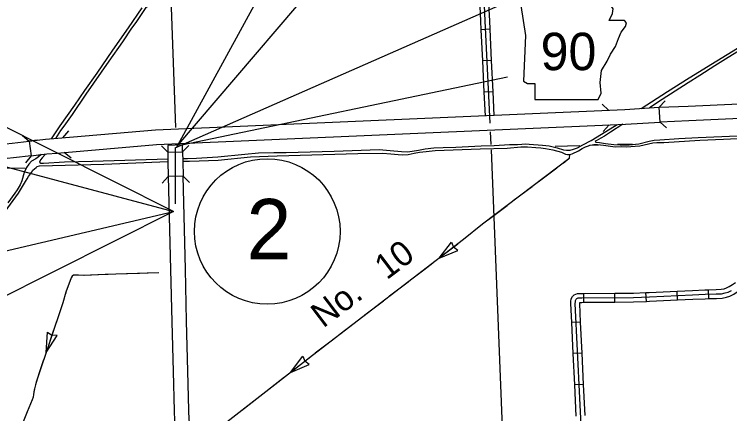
# Model space of a CAD drawing. Extents: x -5566 to 1759129, y -3726 to 731467.
# Drawn here: x -4834.6 to -4742.8, y 279.5 to 330.8 of the extents above; entities that cross this region are included whole.
import ezdxf

# ---------------------------------------------------------------- set-up
doc = ezdxf.new("R2010")
doc.units = 0
doc.layers.add('Default', color=7, linetype='Continuous')

msp = doc.modelspace()

# ---------------------------------------------------------------- linework, layer by layer
at = {"layer": 'Default'}
for p, q in [((-5045.078, 367.089), (-4814.177, 305.513)), ((-4773.531, 328.908), (-4774.669, 328.854)), ((-4773.339, 324.903), (-4774.477, 324.849)), ((-4773.148, 320.898), (-4774.286, 320.844)), ((-4813.973, 313.686), (-4813.973, 306.506)), ((-5037.982, 253.015), (-4814.177, 305.513)), ((-4780.075, 299.507), (-4778.488, 301.574)), ((-4778.488, 301.574), (-4778.222, 300.933)), ((-4780.075, 299.507), (-4777.667, 300.504)), ((-4777.667, 300.504), (-4778.217, 300.926)), ((-4761.516, 293.849), (-4761.524, 294.988)), ((-4757.507, 293.876), (-4757.515, 295.015)), ((-4753.475, 293.973), (-4753.531, 295.11)), ((-4749.471, 294.16), (-4749.524, 295.298)), ((-4745.473, 294.326), (-4745.51, 295.464)), ((-4761.915, 291.318), (-4763.053, 291.264)), ((-4830.53, 287.413), (-4830.363, 290.014)), ((-4830.53, 287.413), (-4829.084, 289.582)), ((-4830.363, 290.014), (-4829.785, 289.629)), ((-4829.084, 289.582), (-4829.776, 289.627)), ((-4799.146, 284.84), (-4797.576, 286.921)), ((-4797.576, 286.921), (-4797.306, 286.282)), ((-4761.727, 287.312), (-4762.865, 287.259)), ((-4799.146, 284.84), (-4796.746, 285.858)), ((-4796.746, 285.858), (-4797.3, 286.275)), ((-4761.538, 283.307), (-4762.676, 283.253))]:
    msp.add_line(p, q, dxfattribs=at)
for points in [[(-4813.759, 313.857), (-4581.459, 585.645), (-4581.459, 585.645)], [(-4813.973, 313.686), (-4397.101, 497.071), (-4397.101, 497.071)], [(-4813.622, 314.016), (-4813.622, 314.016), (-4788.986, 359.2), (-4781.856, 351.37)], [(-4696.252, 355.061), (-4696.632, 354.686), (-4697.139, 354.156), (-4698.831, 353.208), (-4705.395, 349.146), (-4717.477, 341.348), (-4731.156, 332.251), (-4732.102, 331.642), (-4732.867, 331.328), (-4733.4, 331.136), (-4733.902, 330.892), (-4734.572, 330.459), (-4742.996, 325.302), (-4744.672, 324.236), (-4746.615, 322.956), (-4748.105, 322.025), (-4751.473, 319.9), (-4753.098, 318.821)], [(-4807.443, 346.646), (-4810.466, 342.198), (-4812.338, 339.431), (-4813.061, 338.397), (-4815.169, 335.265), (-4815.226, 335.212), (-4816.37, 333.578), (-4816.913, 332.809), (-4817.113, 332.456), (-4817.651, 331.767), (-4817.704, 331.713), (-4818.988, 329.775), (-4819.546, 329.036), (-4820.713, 327.31), (-4822.48, 324.819), (-4825.42, 320.583), (-4827.194, 317.972), (-4828.239, 316.463), (-4828.664, 315.919), (-4829.314, 314.906)], [(-4814.599, 335.359), (-4813.909, 316.294)], [(-4773.525, 316.866), (-4774.152, 329.976), (-4774.348, 334.007)], [(-4774.669, 328.854), (-4774.721, 329.948), (-4774.863, 332.859)], [(-4773.531, 328.908), (-4773.583, 330.003), (-4773.725, 332.914)], [(-4754.128, 318.759), (-4750.752, 320.921), (-4747.973, 322.677), (-4744.417, 324.862), (-4740.467, 327.31), (-4736.357, 329.733), (-4733.777, 331.269), (-4732.753, 331.827), (-4731.996, 332.156), (-4731.432, 332.577), (-4730.561, 333.153)], [(-4818.247, 331.657), (-4820.008, 329.083), (-4822, 326.216), (-4824.011, 323.288), (-4825.578, 321.057), (-4826.866, 319.173), (-4828.773, 316.526), (-4829.874, 314.859)], [(-4774.477, 324.849), (-4774.669, 328.854)], [(-4773.339, 324.903), (-4773.531, 328.908)], [(-4814.177, 305.513), (-4814.177, 305.513), (-4860.149, 328.644), (-4861.555, 318.147)], [(-4774.286, 320.844), (-4774.477, 324.849)], [(-4773.148, 320.898), (-4773.339, 324.903)], [(-4813.108, 314.066), (-4771.285, 322.799)], [(-4774.139, 317.783), (-4774.286, 320.844)], [(-4773.001, 317.839), (-4773.148, 320.898)], [(-4751.821, 318.897), (-4751.056, 319.742)], [(-4751.821, 318.897), (-4748.112, 319.035), (-4735.949, 319.604), (-4734.369, 319.692), (-4734.52, 319.478), (-4734.628, 319.185), (-4734.685, 318.866), (-4734.649, 318.572), (-4734.577, 318.335), (-4734.448, 318.093), (-4734.335, 317.944), (-4734.179, 317.802)], [(-4816.483, 315.999), (-4756.262, 318.631), (-4751.821, 318.897)], [(-4759.172, 319.31), (-4758.332, 318.541)], [(-4734.179, 317.802), (-4735.851, 317.708), (-4748.032, 317.139), (-4751.726, 317.001), (-4751.821, 318.897)], [(-4816.361, 314.104), (-4756.151, 316.736), (-4751.726, 317.001)], [(-4750.881, 316.237), (-4751.726, 317.001)], [(-4831.677, 314.67), (-4832.68, 314.552), (-4831.66, 314.672), (-4830.616, 314.796), (-4829.028, 314.931), (-4816.475, 316)], [(-4812.996, 312.306), (-4812.391, 312.302), (-4811.206, 312.381), (-4808.477, 312.534), (-4805.021, 312.875), (-4803.268, 313.057), (-4801.289, 313.072), (-4799.709, 313.092), (-4793.544, 313.266), (-4787.763, 313.469), (-4786.373, 313.34), (-4784.919, 313.218), (-4784.105, 313.189), (-4782.722, 313.4), (-4781.876, 313.564), (-4780.764, 313.682), (-4779.581, 313.749), (-4777.926, 313.778), (-4774.666, 313.94), (-4773.035, 314.006), (-4771.043, 314.1), (-4770.008, 314.134), (-4769.463, 314.153), (-4769.049, 314.19), (-4768.531, 314.164), (-4766.832, 314.042), (-4765.938, 313.93), (-4764.922, 313.676), (-4764.101, 313.43), (-4763.718, 313.369), (-4763.258, 313.404), (-4762.826, 313.507), (-4762.306, 313.695), (-4761.65, 314.089), (-4760.561, 314.615), (-4757.572, 316.454), (-4757.241, 316.688)], [(-4756.501, 316.72), (-4758.065, 315.715), (-4758.853, 315.187), (-4759.336, 314.918), (-4759.645, 314.746), (-4759.939, 314.589), (-4760.061, 314.514), (-4759.958, 314.42), (-4759.505, 314.374), (-4758.726, 314.23), (-4757.664, 314.109), (-4756.846, 314.072), (-4755.696, 314.084), (-4754.458, 314.222), (-4753.124, 314.557), (-4752.474, 314.661), (-4751.744, 314.702), (-4749.307, 314.904), (-4746.846, 315.005), (-4739.766, 315.315)], [(-4758.249, 316.644), (-4759.018, 315.804)], [(-4833.575, 315.257), (-4832.68, 314.552)], [(-4828.356, 314.988), (-4827.622, 315.859)], [(-4812.992, 311.992), (-4812.104, 311.996), (-4808.423, 312.106), (-4804.27, 312.543), (-4800.874, 312.671), (-4790.495, 312.961), (-4787.357, 312.989), (-4786.292, 312.931), (-4785.324, 312.824), (-4784.754, 312.796), (-4784.056, 312.825), (-4783.264, 312.987), (-4782.592, 313.13), (-4781.752, 313.232), (-4780.585, 313.338), (-4774.818, 313.558), (-4771.336, 313.649), (-4769.612, 313.815), (-4768.721, 313.827), (-4767.686, 313.733), (-4767.01, 313.686), (-4766.427, 313.611), (-4765.477, 313.432), (-4764.386, 313.122), (-4763.864, 312.866), (-4763.62, 312.827), (-4763.506, 312.823), (-4763.342, 312.82), (-4763.008, 312.938), (-4762.198, 313.291), (-4761.729, 313.588), (-4761.295, 313.799), (-4760.92, 313.948), (-4760.748, 314.03), (-4760.447, 314.072), (-4760.231, 314.128), (-4759.751, 314.1), (-4758.98, 314.015), (-4757.805, 313.846), (-4757.401, 313.836), (-4756.733, 313.846), (-4756.055, 313.796), (-4754.311, 313.949), (-4753.202, 314.194), (-4752.637, 314.344), (-4752.12, 314.382), (-4751.246, 314.391), (-4746.613, 314.688), (-4743.585, 314.785), (-4740.036, 314.979)], [(-4773.406, 314.127), (-4773.474, 315.749)], [(-4856.545, 312.213), (-4855.815, 312.238), (-4854.039, 312.293), (-4852.828, 312.353), (-4848.711, 312.761), (-4847.151, 312.947), (-4844.684, 313.184), (-4844.182, 313.237), (-4842.093, 313.462), (-4840.463, 313.635), (-4838.392, 313.881), (-4836.555, 314.114), (-4834.901, 314.288), (-4832.68, 314.552), (-4832.456, 312.667)], [(-4832.456, 312.667), (-4831.517, 312.778), (-4831.437, 312.787), (-4830.424, 312.906), (-4829.095, 313.02), (-4816.35, 314.105)], [(-4813.008, 313.173), (-4813.02, 314.071), (-4814.917, 313.983)], [(-4760.589, 314.031), (-4759.622, 314.061)], [(-4757.188, 314.137), (-4755.321, 314.195)], [(-4814.906, 313.14), (-4815.725, 313.931)], [(-4814.917, 313.983), (-4814.906, 313.14), (-4813.008, 313.173)], [(-4814.906, 313.14), (-4814.89, 311.914), (-4814.842, 309.994)], [(-4812.217, 313.992), (-4813.008, 313.173)], [(-4813.008, 313.173), (-4812.991, 311.95), (-4812.944, 310.041)], [(-4771.764, 273.516), (-4773.376, 313.42)], [(-4765.192, 313.888), (-4762.007, 313.987)], [(-4832.456, 312.667), (-4834.69, 312.401), (-4836.336, 312.228), (-4838.16, 311.997), (-4840.251, 311.748), (-4841.892, 311.574), (-4843.98, 311.349), (-4844.493, 311.295), (-4846.948, 311.059), (-4848.505, 310.873), (-4852.687, 310.459), (-4853.963, 310.396), (-4855.753, 310.34), (-4856.481, 310.316), (-4856.545, 312.213)], [(-4831.17, 312.819), (-4831.521, 312.514), (-4831.841, 312.295), (-4832.391, 311.963), (-4832.751, 311.578), (-4833.046, 311.152), (-4833.35, 310.535), (-4833.636, 309.466), (-4833.837, 308.92), (-4834.229, 308.288), (-4834.529, 307.846), (-4835.448, 306.638)], [(-4763.342, 312.82), (-4763.384, 312.316), (-4763.42, 312.254), (-4774.516, 303.871), (-4776.93, 301.919), (-4796.328, 287.04), (-4812.156, 274.681), (-4814.523, 272.847), (-4815.12, 272.263), (-4815.497, 271.946), (-4816.06, 271.595), (-4816.797, 271.127), (-4817.39, 270.57), (-4817.892, 270.067), (-4818.359, 269.474), (-4818.773, 268.881), (-4818.872, 268.556), (-4819.354, 267.923), (-4820.03, 266.944), (-4826.828, 257.914), (-4833.291, 249.226)], [(-4832.456, 312.666), (-4833.161, 311.772)], [(-4830.605, 312.891), (-4831.025, 312.401), (-4831.254, 312.138), (-4831.353, 311.861), (-4831.194, 311.717)], [(-4831.194, 311.717), (-4830.866, 311.702), (-4828.168, 311.872), (-4824.577, 311.977), (-4814.895, 312.292)], [(-4827.324, 312.362), (-4828.195, 313.096)], [(-4763.342, 312.82), (-4763.384, 312.316), (-4763.42, 312.254), (-4764.159, 311.696)], [(-4835.8, 305.522), (-4834.072, 307.871), (-4833.162, 309.363), (-4832.96, 309.719), (-4832.782, 309.988), (-4832.644, 310.189), (-4832.413, 310.531), (-4832.244, 310.817), (-4831.808, 311.173), (-4831.682, 311.309)], [(-4831.682, 311.309), (-4831.364, 311.374), (-4823.099, 311.596), (-4814.89, 311.939)], [(-4844.009, 311.106), (-4833.222, 311.095)], [(-4764.959, 311.092), (-4767.358, 309.279)], [(-4815.627, 309.168), (-4814.842, 309.994)], [(-4812.944, 310.041), (-4814.842, 309.994), (-4814.543, 298.066), (-4814.387, 291.365), (-4814.21, 284.951), (-4814.096, 279.922), (-4814.04, 278.644), (-4814.022, 278.343), (-4813.987, 278.08), (-4813.947, 277.819), (-4813.875, 277.357), (-4813.783, 276.994), (-4813.617, 276.393)], [(-4813.617, 276.393), (-4811.787, 276.901), (-4811.948, 277.479), (-4812.012, 277.736), (-4812.071, 278.109), (-4812.107, 278.349), (-4812.131, 278.526), (-4812.144, 278.743), (-4812.198, 279.985), (-4812.312, 284.999), (-4812.489, 291.413), (-4812.645, 298.112), (-4812.944, 310.041)], [(-4812.944, 310.041), (-4812.118, 309.256)], [(-4768.158, 308.675), (-4770.558, 306.862)], [(-4771.357, 306.258), (-4773.757, 304.445)], [(-4814.177, 305.513), (-4860.149, 282.381), (-4861.753, 294.353)], [(-4774.556, 303.839), (-4776.894, 301.948)], [(-4777.689, 301.337), (-4780.075, 299.507)], [(-4780.87, 298.897), (-4782.063, 297.982)], [(-4816.044, 297.651), (-4822.959, 297.423), (-4825.783, 297.302), (-4826.35, 297.321), (-4826.703, 297.321), (-4827, 297.339), (-4827.186, 297.228), (-4827.297, 297.005), (-4827.975, 295.146), (-4828.379, 293.775), (-4831.686, 283.994), (-4831.906, 283.248), (-4832.028, 282.737), (-4832.084, 282.324), (-4832.123, 282.004), (-4832.19, 281.69), (-4832.297, 281.348), (-4832.965, 279.768), (-4835.343, 273.767)], [(-4818.549, 297.569), (-4821.555, 297.469)], [(-4816.044, 297.651), (-4817.547, 297.602)], [(-4782.063, 297.982), (-4783.256, 297.066)], [(-4826.563, 297.321), (-4826.703, 297.321), (-4827, 297.339), (-4827.186, 297.228), (-4827.297, 297.005), (-4827.975, 295.146), (-4828.011, 295.026)], [(-4822.557, 297.436), (-4822.959, 297.423), (-4825.561, 297.312)], [(-4784.052, 296.456), (-4786.438, 294.626)], [(-4745.51, 295.464), (-4744.536, 295.496), (-4743.889, 295.518), (-4743.496, 295.601), (-4743.202, 295.689), (-4742.849, 295.872), (-4742.445, 296.144), (-4742.027, 296.406)], [(-4763.053, 291.264), (-4763.167, 293.688), (-4763.16, 293.967), (-4763.13, 294.282), (-4762.948, 294.594), (-4762.731, 294.825), (-4762.335, 294.986), (-4761.773, 294.986), (-4761.524, 294.988)], [(-4761.738, 275.443), (-4762.598, 293.694), (-4762.591, 293.932), (-4762.575, 294.103), (-4762.488, 294.25), (-4762.4, 294.345), (-4762.223, 294.417), (-4761.771, 294.417), (-4755.135, 294.462), (-4753.084, 294.562), (-4747.552, 294.819), (-4745.949, 294.88), (-4744.517, 294.926)], [(-4761.524, 294.988), (-4757.515, 295.015)], [(-4757.515, 295.015), (-4755.15, 295.032), (-4753.531, 295.11)], [(-4753.531, 295.11), (-4753.111, 295.131), (-4749.524, 295.298)], [(-4749.524, 295.298), (-4747.577, 295.388), (-4745.969, 295.45), (-4745.51, 295.464)], [(-4745.473, 294.326), (-4744.498, 294.357), (-4743.751, 294.383), (-4743.214, 294.496), (-4742.773, 294.628), (-4742.266, 294.89), (-4741.823, 295.19), (-4741.422, 295.441)], [(-4744.517, 294.926), (-4743.82, 294.95), (-4743.355, 295.048), (-4742.988, 295.158), (-4742.557, 295.381)], [(-4828.294, 294.064), (-4828.379, 293.775), (-4829.245, 291.212)], [(-4787.233, 294.016), (-4789.62, 292.186)], [(-4761.915, 291.318), (-4762.028, 293.699), (-4762.024, 293.847), (-4761.769, 293.847), (-4761.516, 293.849)], [(-4761.516, 293.849), (-4757.507, 293.876)], [(-4757.507, 293.876), (-4755.119, 293.893), (-4753.475, 293.973)], [(-4753.475, 293.973), (-4753.057, 293.993), (-4749.471, 294.16)], [(-4749.471, 294.16), (-4747.528, 294.25), (-4745.929, 294.311), (-4745.473, 294.326)], [(-4790.415, 291.576), (-4792.801, 289.745)], [(-4762.865, 287.259), (-4763.053, 291.264)], [(-4761.727, 287.312), (-4761.915, 291.318)], [(-4829.567, 290.262), (-4830.53, 287.413)], [(-4793.597, 289.135), (-4795.983, 287.305)], [(-4796.775, 286.691), (-4799.146, 284.84)], [(-4762.676, 283.253), (-4762.865, 287.259)], [(-4761.538, 283.307), (-4761.727, 287.312)], [(-4830.851, 286.464), (-4831.333, 285.039)], [(-4831.333, 285.039), (-4831.686, 283.994), (-4831.799, 283.61)], [(-4799.936, 284.223), (-4801.121, 283.298)], [(-4801.121, 283.298), (-4802.306, 282.372)], [(-4762.487, 279.248), (-4762.676, 283.253)], [(-4761.349, 279.302), (-4761.538, 283.307)], [(-4832.042, 282.638), (-4832.084, 282.324), (-4832.123, 282.004), (-4832.19, 281.69), (-4832.297, 281.348), (-4832.955, 279.793)], [(-4803.096, 281.755), (-4805.466, 279.905)]]:
    msp.add_lwpolyline(points, dxfattribs=at)
msp.add_lwpolyline([(-4769.573, 331.966), (-4768.995, 328.112), (-4769.252, 322.266), (-4768.738, 321.945), (-4767.775, 321.945), (-4767.775, 319.889), (-4759.681, 319.889), (-4759.295, 320.724), (-4759.424, 322.073), (-4759.231, 323.615), (-4758.524, 324.836), (-4758.075, 325.735), (-4757.432, 326.699), (-4757.047, 327.726), (-4756.726, 328.561), (-4756.147, 329.268), (-4756.019, 329.718), (-4756.276, 330.039), (-4758.267, 330.039), (-4757.818, 330.938), (-4757.753, 331.516), (-4758.02, 331.96)], close=True, dxfattribs=at)
msp.add_circle((-4802.138, 302.954), 9.341, dxfattribs=at)

# ---------------------------------------------------------------- texts
for s, height, p in [('90', 4.8071, (-4767.048, 323.659)), ('2', 7.746, (-4804.8, 299.371))]:
    msp.add_text(s, height=height, dxfattribs=at).set_placement(p)
msp.add_text('No.   10', height=3.2048, rotation=37.14673, dxfattribs=at).set_placement((-4794.964, 290.471))

doc.saveas('drawing.dxf')
